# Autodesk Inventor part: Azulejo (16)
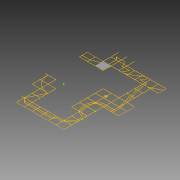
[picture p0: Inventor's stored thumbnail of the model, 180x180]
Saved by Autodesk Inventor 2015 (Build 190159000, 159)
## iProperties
Created: 2015-04
Part Number: Azulejo (16)
Material: Genérico
Document SubType Name: Modeling
Designer: Felipe
Density: 1 g/cm^3
Appearance: Padrão
Author: Felipe
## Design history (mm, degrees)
sketch "Sketch1"
  geometry: L1 (-1510, -7490)-(-1510, -6010); L2 (992.445, 7510)-(992.445, 8990); L3 (1012.445, 7510)-(1012.445, 8990); L4 (-3010, -1490)-(-3010, -10); L5 (-1510, 7490)-(-2990, 7490); L6 (-2990, 10)-(-1510, 10); L7 (-1510, -10)-(-2990, -10); L8 (-1510, -1490)-(-1510, -10); L9 (-10, 9010)-(-10, 10490); L10 (-10, 7510)-(-10, 8990); L11 (-10, 7490)-(-1490, 7490); L12 (-1490, 6010)-(-10, 6010); L13 (-10, 5990)-(-1490, 5990); L14 (-1490, -10)-(-1490, -1490); L15 (-1490, -1490)-(-10, -1490); L16 (-10, -1510)-(-1490, -1510); L17 (-10, -2990)-(-10, -1510); L18 (-10, -5990)-(-10, -4510); L19 (-1490, -7490)-(-10, -7490); L20 (10, 8990)-(10, 7510); L21 (1490, 7510)-(1490, 8990); L22 (10, 6010)-(1490, 6010); L23 (1490, 6010)-(1490, 7490); L24 (1490, 5990)-(10, 5990); L25 (4490, -6010)-(3010, -6010); L26 (10, -1510)-(10, -2990); L27 (10, -3010)-(10, -4490); L28 (10, -4510)-(10, -5990); L29 (10, -5990)-(1490, -5990); L30 (1490, -6010)-(10, -6010); L31 (10, -7490)-(1490, -7490); L32 (2990, 9010)-(2990, 10490); L33 (1510, 8990)-(1510, 7510); L34 (1510, 7510)-(2990, 7510); L35 (2990, 7490)-(1510, 7490); L36 (1510, 7490)-(1510, 6010); L37 (1510, -5990)-(2990, -5990); L38 (2990, -6010)-(1510, -6010); L39 (1510, -7490)-(2990, -7490); L40 (3010, 10490)-(3010, 9010); L41 (3010, 9010)-(4490, 9010); L42 (4490, 8990)-(3010, 8990); L43 (4490, 7490)-(3010, 7490); L44 (4490, 1510)-(4490, 2990); L45 (4490, 10)-(4490, 1490); L46 (4490, -1490)-(4490, -10); L47 (4490, -2990)-(4490, -1510); L48 (3010, -5990)-(4490, -5990); L49 (3010, -7490)-(4490, -7490); L50 (4510, 9010)-(5990, 9010); L51 (5990, 8990)-(4510, 8990); L52 (4510, 7510)-(5990, 7510); L53 (5990, 7490)-(4510, 7490); L54 (4510, 3010)-(5990, 3010); L55 (5990, 2990)-(4510, 2990); L56 (4510, 2990)-(4510, 1510); L57 (4510, 1510)-(5990, 1510); L58 (5990, 1510)-(5990, 1740.185); L59 (5990, 1760.2)-(5990, 2259.8); L60 (5990, 2279.815)-(5990, 2990); L61 (5990, 1490)-(4510, 1490); L62 (4510, 1490)-(4510, 10); L63 (4510, 10)-(5990, 10); L64 (5990, 10)-(5990, 1490)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; A1 r 250 centre (6000, 2010) between (5990, 2259.8) and (5990, 1760.2); A2 r 250 centre (6000, 2010) between (6010, 1760.2) and (6010, 2259.8); A3 r 270 centre (6000, 2010) between (5990, 2279.815) and (5990, 1740.185); A4 r 270 centre (6000, 2010) between (6010, 1740.185) and (6010, 2279.815); A5 r 3010.017 centre (0, 0) between (-1490, -2615.358) and (-346.554, -2990); A6 r 2990.017 centre (0, 0) between (-1490, -2592.316) and (-10, -2990); A7 r 3010.017 centre (0, 0) between (-2603.863, -1510) and (-1510, -2603.863); A8 r 2990.017 centre (0, 0) between (-2580.717, -1510) and (-1510, -2580.717); A9 r 3010.017 centre (0, 0) between (-2990, -346.554) and (-2615.358, -1490); A10 r 2990.017 centre (0, 0) between (-2990, -10) and (-2592.316, -1490); A11 r 2131.367 centre (7500, -1500) between (7490, 631.344) and (6010, 24.017); A12 r 2131.367 centre (7500, -1500) between (5975.983, -10) and (5368.656, -1490); A13 r 2131.367 centre (7500, -1500) between (5368.656, -1510) and (5975.983, -2990); A14 r 2131.367 centre (7500, -1500) between (6010, -3024.017) and (7190, -3608.703); A15 r 1831.367 centre (7500, -1500) between (7490.321, 331.342) and (6463.753, 10); A16 r 1831.367 centre (7500, -1500) between (6435.196, -10) and (6010, -435.196); A17 r 1831.367 centre (7500, -1500) between (5990, -463.753) and (5668.66, -1490); A18 r 1831.367 centre (7500, -1500) between (5668.66, -1510) and (5990, -2536.247); A19 r 1831.367 centre (7500, -1500) between (6010, -2564.804) and (6435.196, -2990); A20 r 1831.367 centre (7500, -1500) between (6463.753, -3010) and (7490, -3331.34); A21 r 2111.367 centre (7500, -1500) between (7490.047, 611.344) and (6024.272, 10); A22 r 2111.367 centre (7500, -1500) between (5990, -24.272) and (5388.656, -1490); A23 r 2111.367 centre (7500, -1500) between (5388.656, -1510) and (5990, -2975.728); A24 r 2111.367 centre (7500, -1500) between (6024.272, -3010) and (7210, -3591.357); A25 r 1811.367 centre (7500, -1500) between (7490.374, 311.342) and (6499.524, 10); A26 r 1811.367 centre (7500, -1500) between (6469.975, -10) and (6010, -469.975); A27 r 1811.367 centre (7500, -1500) between (5990, -499.524) and (5688.66, -1490); A28 r 1811.367 centre (7500, -1500) between (5688.66, -1510) and (5990, -2500.476); A29 r 1811.367 centre (7500, -1500) between (6010, -2530.025) and (6469.975, -2990); A30 r 1811.367 centre (7500, -1500) between (6499.524, -3010) and (7490, -3311.34); A31 r 449.871 centre (7499.449, -4060.672) between (7510, -4510.419) and (7521.546, -4510); 4 further points
  constraints: 1040 end point, 64 point on circle, 31 centre point, 13 point on line, 1 other
extrude "Extrusion1" new body sketch "Sketch1" distance "d0" = 60; taper "d1" = 0 deg
extrude "Extrusion2" new body sketch "Sketch1" distance "d2" = 60; taper "d3" = 0 deg
body "Solid1"
body "Solid2"
